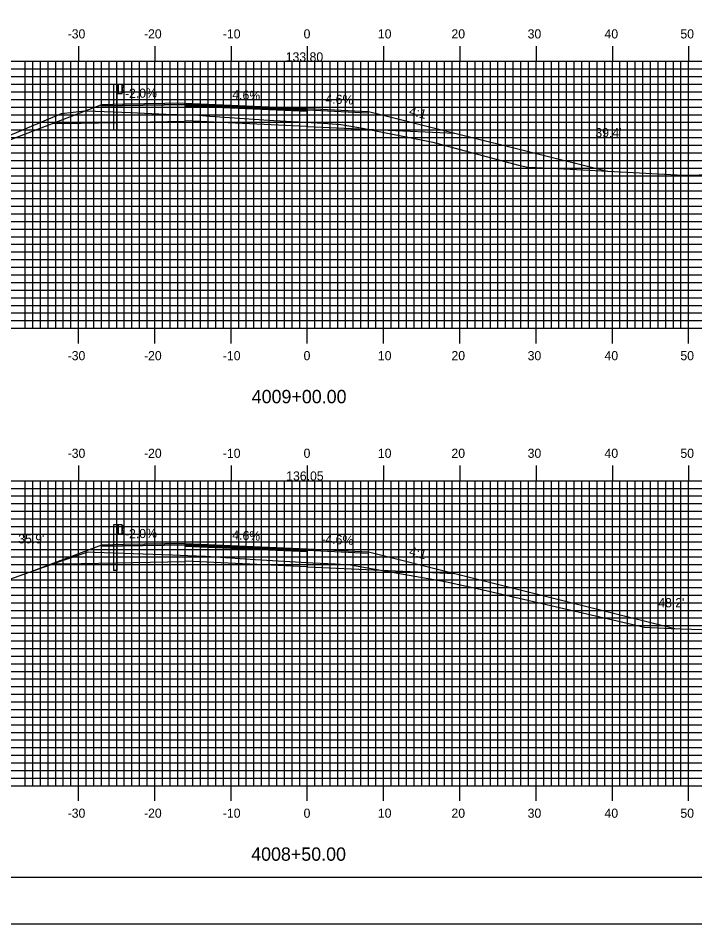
# Model space of a CAD drawing. Extents: x 852147 to 852490, y 364661 to 364881.
# Drawn here: x 852274.8 to 852363.6, y 364661.3 to 364780 of the extents above; entities that cross this region are included whole.
import ezdxf

# ---------------------------------------------------------------- set-up
doc = ezdxf.new("R2010")
doc.units = 0
for name, color, linetype in [('ANNOTATION', 7, 'Continuous'), ('BORDER', 7, 'Continuous'), ('D_Guardrail_Beam_Lt', 7, 'Continuous'), ('D_Roadway_Centerline_Text', 7, 'Continuous'), ('D_Roadway_Edge_Shoulder', 7, 'Continuous'), ('D_Roadway_Edge_TW', 7, 'Continuous'), ('D_Roadway_Pavement', 7, 'Continuous'), ('D_Roadway_SlopeLines', 7, 'Continuous'), ('D_Roadway_SubGrade', 7, 'Continuous'), ('D_Text_Standard', 7, 'Continuous'), ('H_V ANNOTATION', 7, 'Continuous'), ('M_Roadway_Centerline', 7, 'Continuous'), ('MAJOR', 7, 'Continuous'), ('MINOR', 7, 'Continuous'), ('PLOT BOUNDARY', 7, 'Continuous'), ('S_Roadway_Centerline', 7, 'Continuous')]:
    doc.layers.add(name, color=color, linetype=linetype)

msp = doc.modelspace()

# ---------------------------------------------------------------- linework, layer by layer
at = {"layer": 'ANNOTATION'}
msp.add_line((852280.84, 364766.23), (852279.36, 364766.23), dxfattribs=at)
at = {"layer": 'BORDER'}
msp.add_lwpolyline([(852163.16, 364667.37), (852483.16, 364667.37), (852483.16, 364877.37), (852163.16, 364877.37)], close=True, dxfattribs=at)
at = {"layer": 'D_Guardrail_Beam_Lt'}
for p, q in [((852287.33, 364771.33), (852287.33, 364765.33)), ((852287.8, 364771.33), (852287.33, 364771.33)), ((852288.48, 364771.33), (852287.8, 364771.33)), ((852287.8, 364771.33), (852287.8, 364770.16)), ((852287.86, 364771.33), (852287.86, 364770.16)), ((852287.96, 364771.33), (852287.96, 364770.16)), ((852288.48, 364770.16), (852288.48, 364771.33)), ((852288.48, 364771.24), (852288.56, 364771.23)), ((852288.49, 364770.78), (852288.49, 364770.71)), ((852288.72, 364770.98), (852288.52, 364770.84)), ((852288.52, 364770.64), (852288.72, 364770.51)), ((852288.57, 364771.22), (852288.72, 364771.12)), ((852287.8, 364770.16), (852288.48, 364770.16)), ((852287.82, 364765.33), (852287.82, 364770.16)), ((852288.56, 364770.26), (852288.48, 364770.24)), ((852288.72, 364770.36), (852288.57, 364770.26)), ((852287.82, 364765.33), (852287.33, 364765.33)), ((852287.33, 364713.58), (852287.33, 364707.58)), ((852287.8, 364713.58), (852287.33, 364713.58)), ((852288.48, 364713.58), (852287.8, 364713.58)), ((852287.8, 364713.58), (852287.8, 364712.41)), ((852287.86, 364713.58), (852287.86, 364712.41)), ((852287.96, 364713.58), (852287.96, 364712.41)), ((852288.48, 364712.41), (852288.48, 364713.58)), ((852287.8, 364712.41), (852288.48, 364712.41)), ((852287.82, 364707.58), (852287.82, 364712.41)), ((852288.48, 364713.49), (852288.56, 364713.48)), ((852288.56, 364712.51), (852288.48, 364712.49)), ((852288.49, 364713.03), (852288.49, 364712.96)), ((852288.72, 364713.23), (852288.52, 364713.09)), ((852288.52, 364712.89), (852288.72, 364712.76)), ((852288.57, 364713.47), (852288.72, 364713.37)), ((852288.72, 364712.61), (852288.57, 364712.51)), ((852287.82, 364707.58), (852287.33, 364707.58))]:
    msp.add_line(p, q, dxfattribs=at)
for centre, major_axis, start_param, end_param in [((852288.57, 364770.78), (-0.0789, 0), 5.323254, 6.283185), ((852288.57, 364770.71), (-0.0789, 0), 6.283185, 7.243116), ((852288.55, 364771.19), (0.0417, 0), 0.959931, 1.376053), ((852288.67, 364771.05), (0.0877, 0), 5.323254, 7.243116), ((852288.55, 364770.3), (0.0417, 0), 4.907132, 5.323254), ((852288.67, 364770.44), (0.0877, 0), 5.323254, 7.243116), ((852288.57, 364713.03), (-0.0789, 0), 5.323254, 6.283185), ((852288.57, 364712.96), (-0.0789, 0), 6.283185, 7.243116), ((852288.55, 364713.44), (0.0417, 0), 0.959931, 1.376053), ((852288.55, 364712.55), (0.0417, 0), 4.907132, 5.323254), ((852288.67, 364713.3), (0.0877, 0), 5.323254, 7.243116), ((852288.67, 364712.69), (0.0877, 0), 5.323254, 7.243116)]:
    msp.add_ellipse(centre, major_axis=major_axis, ratio=0.995501, start_param=start_param, end_param=end_param, dxfattribs=at)
at = {"layer": 'D_Roadway_Edge_Shoulder'}
for points in [[(852296.76, 364768.9), (852288.76, 364768.74), (852288.76, 364768.74), (852285.76, 364768.68), (852285.76, 364768.52), (852296.76, 364768.71)], [(852296.76, 364711.15), (852288.76, 364710.99), (852288.76, 364710.99), (852285.76, 364710.93), (852285.76, 364710.77), (852296.76, 364710.96)]]:
    msp.add_lwpolyline(points, close=True, dxfattribs=at)
at = {"layer": 'D_Roadway_Edge_TW'}
for p, q in [((852312.76, 364768.17), (852320.76, 364767.8)), ((852312.76, 364710.42), (852320.76, 364710.05))]:
    msp.add_line(p, q, dxfattribs=at)
for points in [[(852296.76, 364768.9), (852312.76, 364768.17), (852312.76, 364768), (852296.76, 364768.71)], [(852296.76, 364711.15), (852312.76, 364710.42), (852312.76, 364710.25), (852296.76, 364710.96)]]:
    msp.add_lwpolyline(points, close=True, dxfattribs=at)
for points in [[(852312.76, 364768), (852320.76, 364767.63), (852320.76, 364767.8)], [(852312.76, 364710.25), (852320.76, 364709.88), (852320.76, 364710.05)]]:
    msp.add_lwpolyline(points, dxfattribs=at)
at = {"layer": 'D_Roadway_Pavement'}
for points in [[(852296.76, 364768.71), (852312.76, 364768), (852312.76, 364767.83), (852296.76, 364768.55)], [(852296.76, 364710.96), (852312.76, 364710.25), (852312.76, 364710.08), (852296.76, 364710.8)]]:
    msp.add_lwpolyline(points, close=True, dxfattribs=at)
for points in [[(852296.76, 364768.71), (852296.76, 364768.55)], [(852312.76, 364768), (852312.76, 364767.83)], [(852312.76, 364768), (852312.76, 364767.83)], [(852296.76, 364710.96), (852296.76, 364710.8)], [(852312.76, 364710.25), (852312.76, 364710.08)], [(852312.76, 364710.25), (852312.76, 364710.08)]]:
    msp.add_lwpolyline(points, dxfattribs=at)
at = {"layer": 'D_Roadway_SlopeLines'}
for p, q in [((852285.76, 364768.68), (852231.3, 364747.76)), ((852285.76, 364710.93), (852276.85, 364707.57)), ((852280.84, 364708.48), (852279.16, 364708.44))]:
    msp.add_line(p, q, dxfattribs=at)
for points in [[(852320.76, 364767.8), (852332.29, 364764.92), (852352.12, 364759.96)], [(852320.76, 364710.05), (852332.29, 364707.17), (852360.97, 364700)]]:
    msp.add_lwpolyline(points, dxfattribs=at)
at = {"layer": 'D_Roadway_SubGrade'}
for p, q in [((852312.76, 364765.83), (852332.05, 364764.97)), ((852312.76, 364708.08), (852332.05, 364707.22))]:
    msp.add_line(p, q, dxfattribs=at)
for points in [[(852280.84, 364766.23), (852296.76, 364766.54), (852296.76, 364768.54), (852296.76, 364768.71), (852285.76, 364768.52), (852285.76, 364768.68)], [(852280.84, 364708.48), (852296.76, 364708.79), (852296.76, 364710.79), (852296.76, 364710.96), (852285.76, 364710.77), (852285.76, 364710.93)]]:
    msp.add_lwpolyline(points, dxfattribs=at)
for points in [[(852296.76, 364768.55), (852312.76, 364767.83), (852312.76, 364765.83), (852296.76, 364766.55)], [(852296.76, 364710.8), (852312.76, 364710.08), (852312.76, 364708.08), (852296.76, 364708.8)]]:
    msp.add_lwpolyline(points, close=True, dxfattribs=at)
at = {"layer": 'MAJOR'}
for p, q in [((852282.76, 364776.37), (852282.76, 364774.37)), ((852292.76, 364776.37), (852292.76, 364774.37)), ((852302.76, 364776.37), (852302.76, 364774.37)), ((852312.76, 364776.37), (852312.76, 364774.37)), ((852322.76, 364776.37), (852322.76, 364774.37)), ((852332.76, 364776.37), (852332.76, 364774.37)), ((852342.76, 364776.37), (852342.76, 364774.37)), ((852352.76, 364776.37), (852352.76, 364774.37)), ((852362.76, 364776.37), (852362.76, 364774.37)), ((852172.76, 364774.37), (852452.76, 364774.37)), ((852172.76, 364774.37), (852452.76, 364774.37)), ((852282.76, 364739.37), (852282.76, 364774.37)), ((852292.76, 364739.37), (852292.76, 364774.37)), ((852302.76, 364739.37), (852302.76, 364774.37)), ((852312.76, 364739.37), (852312.76, 364774.37)), ((852322.76, 364739.37), (852322.76, 364774.37)), ((852332.76, 364739.37), (852332.76, 364774.37)), ((852342.76, 364739.37), (852342.76, 364774.37)), ((852352.76, 364739.37), (852352.76, 364774.37)), ((852362.76, 364739.37), (852362.76, 364774.37)), ((852172.76, 364769.37), (852452.76, 364769.37)), ((852172.76, 364764.37), (852452.76, 364764.37)), ((852172.76, 364759.37), (852452.76, 364759.37)), ((852172.76, 364754.37), (852452.76, 364754.37)), ((852172.76, 364749.37), (852452.76, 364749.37)), ((852172.76, 364744.37), (852452.76, 364744.37)), ((852172.76, 364739.37), (852452.76, 364739.37)), ((852172.76, 364739.37), (852452.76, 364739.37)), ((852282.76, 364737.37), (852282.76, 364739.37)), ((852292.76, 364737.37), (852292.76, 364739.37)), ((852302.76, 364737.37), (852302.76, 364739.37)), ((852312.76, 364737.37), (852312.76, 364739.37)), ((852322.76, 364737.37), (852322.76, 364739.37)), ((852332.76, 364737.37), (852332.76, 364739.37)), ((852342.76, 364737.37), (852342.76, 364739.37)), ((852352.76, 364737.37), (852352.76, 364739.37)), ((852362.76, 364737.37), (852362.76, 364739.37)), ((852282.76, 364721.37), (852282.76, 364719.37)), ((852292.76, 364721.37), (852292.76, 364719.37)), ((852302.76, 364721.37), (852302.76, 364719.37)), ((852312.76, 364721.37), (852312.76, 364719.37)), ((852322.76, 364721.37), (852322.76, 364719.37)), ((852332.76, 364721.37), (852332.76, 364719.37)), ((852342.76, 364721.37), (852342.76, 364719.37)), ((852352.76, 364721.37), (852352.76, 364719.37)), ((852362.76, 364721.37), (852362.76, 364719.37)), ((852172.76, 364719.37), (852452.76, 364719.37)), ((852172.76, 364719.37), (852452.76, 364719.37)), ((852282.76, 364679.37), (852282.76, 364719.37)), ((852292.76, 364679.37), (852292.76, 364719.37)), ((852302.76, 364679.37), (852302.76, 364719.37)), ((852312.76, 364679.37), (852312.76, 364719.37)), ((852322.76, 364679.37), (852322.76, 364719.37)), ((852332.76, 364679.37), (852332.76, 364719.37)), ((852342.76, 364679.37), (852342.76, 364719.37)), ((852352.76, 364679.37), (852352.76, 364719.37)), ((852362.76, 364679.37), (852362.76, 364719.37)), ((852172.76, 364714.37), (852452.76, 364714.37)), ((852172.76, 364709.37), (852452.76, 364709.37)), ((852172.76, 364704.37), (852452.76, 364704.37)), ((852172.76, 364699.37), (852452.76, 364699.37)), ((852172.76, 364694.37), (852452.76, 364694.37)), ((852172.76, 364689.37), (852452.76, 364689.37)), ((852172.76, 364684.37), (852452.76, 364684.37)), ((852172.76, 364679.37), (852452.76, 364679.37)), ((852172.76, 364679.37), (852452.76, 364679.37)), ((852282.76, 364677.37), (852282.76, 364679.37)), ((852292.76, 364677.37), (852292.76, 364679.37)), ((852302.76, 364677.37), (852302.76, 364679.37)), ((852312.76, 364677.37), (852312.76, 364679.37)), ((852322.76, 364677.37), (852322.76, 364679.37)), ((852332.76, 364677.37), (852332.76, 364679.37)), ((852342.76, 364677.37), (852342.76, 364679.37)), ((852352.76, 364677.37), (852352.76, 364679.37)), ((852362.76, 364677.37), (852362.76, 364679.37))]:
    msp.add_line(p, q, dxfattribs=at)
at = {"layer": 'MINOR'}
for p, q in [((852275.76, 364739.37), (852275.76, 364774.37)), ((852276.76, 364739.37), (852276.76, 364774.37)), ((852277.76, 364739.37), (852277.76, 364774.37)), ((852278.76, 364739.37), (852278.76, 364774.37)), ((852279.76, 364739.37), (852279.76, 364774.37)), ((852280.76, 364739.37), (852280.76, 364774.37)), ((852281.76, 364739.37), (852281.76, 364774.37)), ((852283.76, 364739.37), (852283.76, 364774.37)), ((852284.76, 364739.37), (852284.76, 364774.37)), ((852285.76, 364739.37), (852285.76, 364774.37)), ((852286.76, 364739.37), (852286.76, 364774.37)), ((852287.76, 364739.37), (852287.76, 364774.37)), ((852288.76, 364739.37), (852288.76, 364774.37)), ((852289.76, 364739.37), (852289.76, 364774.37)), ((852290.76, 364739.37), (852290.76, 364774.37)), ((852291.76, 364739.37), (852291.76, 364774.37)), ((852293.76, 364739.37), (852293.76, 364774.37)), ((852294.76, 364739.37), (852294.76, 364774.37)), ((852295.76, 364739.37), (852295.76, 364774.37)), ((852296.76, 364739.37), (852296.76, 364774.37)), ((852297.76, 364739.37), (852297.76, 364774.37)), ((852298.76, 364739.37), (852298.76, 364774.37)), ((852299.76, 364739.37), (852299.76, 364774.37)), ((852300.76, 364739.37), (852300.76, 364774.37)), ((852301.76, 364739.37), (852301.76, 364774.37)), ((852303.76, 364739.37), (852303.76, 364774.37)), ((852304.76, 364739.37), (852304.76, 364774.37)), ((852305.76, 364739.37), (852305.76, 364774.37)), ((852306.76, 364739.37), (852306.76, 364774.37)), ((852307.76, 364739.37), (852307.76, 364774.37)), ((852308.76, 364739.37), (852308.76, 364774.37)), ((852309.76, 364739.37), (852309.76, 364774.37)), ((852310.76, 364739.37), (852310.76, 364774.37)), ((852311.76, 364739.37), (852311.76, 364774.37)), ((852313.76, 364739.37), (852313.76, 364774.37)), ((852314.76, 364739.37), (852314.76, 364774.37)), ((852315.76, 364739.37), (852315.76, 364774.37)), ((852316.76, 364739.37), (852316.76, 364774.37)), ((852317.76, 364739.37), (852317.76, 364774.37)), ((852318.76, 364739.37), (852318.76, 364774.37)), ((852319.76, 364739.37), (852319.76, 364774.37)), ((852320.76, 364739.37), (852320.76, 364774.37)), ((852321.76, 364739.37), (852321.76, 364774.37)), ((852323.76, 364739.37), (852323.76, 364774.37)), ((852324.76, 364739.37), (852324.76, 364774.37)), ((852325.76, 364739.37), (852325.76, 364774.37)), ((852326.76, 364739.37), (852326.76, 364774.37)), ((852327.76, 364739.37), (852327.76, 364774.37)), ((852328.76, 364739.37), (852328.76, 364774.37)), ((852329.76, 364739.37), (852329.76, 364774.37)), ((852330.76, 364739.37), (852330.76, 364774.37)), ((852331.76, 364739.37), (852331.76, 364774.37)), ((852333.76, 364739.37), (852333.76, 364774.37)), ((852334.76, 364739.37), (852334.76, 364774.37)), ((852335.76, 364739.37), (852335.76, 364774.37)), ((852336.76, 364739.37), (852336.76, 364774.37)), ((852337.76, 364739.37), (852337.76, 364774.37)), ((852338.76, 364739.37), (852338.76, 364774.37)), ((852339.76, 364739.37), (852339.76, 364774.37)), ((852340.76, 364739.37), (852340.76, 364774.37)), ((852341.76, 364739.37), (852341.76, 364774.37)), ((852343.76, 364739.37), (852343.76, 364774.37)), ((852344.76, 364739.37), (852344.76, 364774.37)), ((852345.76, 364739.37), (852345.76, 364774.37)), ((852346.76, 364739.37), (852346.76, 364774.37)), ((852347.76, 364739.37), (852347.76, 364774.37)), ((852348.76, 364739.37), (852348.76, 364774.37)), ((852349.76, 364739.37), (852349.76, 364774.37)), ((852350.76, 364739.37), (852350.76, 364774.37)), ((852351.76, 364739.37), (852351.76, 364774.37)), ((852353.76, 364739.37), (852353.76, 364774.37)), ((852354.76, 364739.37), (852354.76, 364774.37)), ((852355.76, 364739.37), (852355.76, 364774.37)), ((852356.76, 364739.37), (852356.76, 364774.37)), ((852357.76, 364739.37), (852357.76, 364774.37)), ((852358.76, 364739.37), (852358.76, 364774.37)), ((852359.76, 364739.37), (852359.76, 364774.37)), ((852360.76, 364739.37), (852360.76, 364774.37)), ((852361.76, 364739.37), (852361.76, 364774.37)), ((852172.76, 364773.37), (852452.76, 364773.37)), ((852172.76, 364772.37), (852452.76, 364772.37)), ((852172.76, 364771.37), (852452.76, 364771.37)), ((852172.76, 364770.37), (852452.76, 364770.37)), ((852172.76, 364768.37), (852452.76, 364768.37)), ((852172.76, 364767.37), (852452.76, 364767.37)), ((852172.76, 364766.37), (852452.76, 364766.37)), ((852172.76, 364765.37), (852452.76, 364765.37)), ((852172.76, 364763.37), (852452.76, 364763.37)), ((852172.76, 364762.37), (852452.76, 364762.37)), ((852172.76, 364761.37), (852452.76, 364761.37)), ((852172.76, 364760.37), (852452.76, 364760.37)), ((852172.76, 364758.37), (852452.76, 364758.37)), ((852172.76, 364757.37), (852452.76, 364757.37)), ((852172.76, 364756.37), (852452.76, 364756.37)), ((852172.76, 364755.37), (852452.76, 364755.37)), ((852172.76, 364753.37), (852452.76, 364753.37)), ((852172.76, 364752.37), (852452.76, 364752.37)), ((852172.76, 364751.37), (852452.76, 364751.37)), ((852172.76, 364750.37), (852452.76, 364750.37)), ((852172.76, 364748.37), (852452.76, 364748.37)), ((852172.76, 364747.37), (852452.76, 364747.37)), ((852172.76, 364746.37), (852452.76, 364746.37)), ((852172.76, 364745.37), (852452.76, 364745.37)), ((852172.76, 364743.37), (852452.76, 364743.37)), ((852172.76, 364742.37), (852452.76, 364742.37)), ((852172.76, 364741.37), (852452.76, 364741.37)), ((852172.76, 364740.37), (852452.76, 364740.37)), ((852172.76, 364718.37), (852452.76, 364718.37)), ((852275.76, 364679.37), (852275.76, 364719.37)), ((852276.76, 364679.37), (852276.76, 364719.37)), ((852277.76, 364679.37), (852277.76, 364719.37)), ((852278.76, 364679.37), (852278.76, 364719.37)), ((852279.76, 364679.37), (852279.76, 364719.37)), ((852280.76, 364679.37), (852280.76, 364719.37)), ((852281.76, 364679.37), (852281.76, 364719.37)), ((852283.76, 364679.37), (852283.76, 364719.37)), ((852284.76, 364679.37), (852284.76, 364719.37)), ((852285.76, 364679.37), (852285.76, 364719.37)), ((852286.76, 364679.37), (852286.76, 364719.37)), ((852287.76, 364679.37), (852287.76, 364719.37)), ((852288.76, 364679.37), (852288.76, 364719.37)), ((852289.76, 364679.37), (852289.76, 364719.37)), ((852290.76, 364679.37), (852290.76, 364719.37)), ((852291.76, 364679.37), (852291.76, 364719.37)), ((852293.76, 364679.37), (852293.76, 364719.37)), ((852294.76, 364679.37), (852294.76, 364719.37)), ((852295.76, 364679.37), (852295.76, 364719.37)), ((852296.76, 364679.37), (852296.76, 364719.37)), ((852297.76, 364679.37), (852297.76, 364719.37)), ((852298.76, 364679.37), (852298.76, 364719.37)), ((852299.76, 364679.37), (852299.76, 364719.37)), ((852300.76, 364679.37), (852300.76, 364719.37)), ((852301.76, 364679.37), (852301.76, 364719.37)), ((852303.76, 364679.37), (852303.76, 364719.37)), ((852304.76, 364679.37), (852304.76, 364719.37)), ((852305.76, 364679.37), (852305.76, 364719.37)), ((852306.76, 364679.37), (852306.76, 364719.37)), ((852307.76, 364679.37), (852307.76, 364719.37)), ((852308.76, 364679.37), (852308.76, 364719.37)), ((852309.76, 364679.37), (852309.76, 364719.37)), ((852310.76, 364679.37), (852310.76, 364719.37)), ((852311.76, 364679.37), (852311.76, 364719.37)), ((852313.76, 364679.37), (852313.76, 364719.37)), ((852314.76, 364679.37), (852314.76, 364719.37)), ((852315.76, 364679.37), (852315.76, 364719.37)), ((852316.76, 364679.37), (852316.76, 364719.37)), ((852317.76, 364679.37), (852317.76, 364719.37)), ((852318.76, 364679.37), (852318.76, 364719.37)), ((852319.76, 364679.37), (852319.76, 364719.37)), ((852320.76, 364679.37), (852320.76, 364719.37)), ((852321.76, 364679.37), (852321.76, 364719.37)), ((852323.76, 364679.37), (852323.76, 364719.37)), ((852324.76, 364679.37), (852324.76, 364719.37)), ((852325.76, 364679.37), (852325.76, 364719.37)), ((852326.76, 364679.37), (852326.76, 364719.37)), ((852327.76, 364679.37), (852327.76, 364719.37)), ((852328.76, 364679.37), (852328.76, 364719.37)), ((852329.76, 364679.37), (852329.76, 364719.37)), ((852330.76, 364679.37), (852330.76, 364719.37)), ((852331.76, 364679.37), (852331.76, 364719.37)), ((852333.76, 364679.37), (852333.76, 364719.37)), ((852334.76, 364679.37), (852334.76, 364719.37)), ((852335.76, 364679.37), (852335.76, 364719.37)), ((852336.76, 364679.37), (852336.76, 364719.37)), ((852337.76, 364679.37), (852337.76, 364719.37)), ((852338.76, 364679.37), (852338.76, 364719.37)), ((852339.76, 364679.37), (852339.76, 364719.37)), ((852340.76, 364679.37), (852340.76, 364719.37)), ((852341.76, 364679.37), (852341.76, 364719.37)), ((852343.76, 364679.37), (852343.76, 364719.37)), ((852344.76, 364679.37), (852344.76, 364719.37)), ((852345.76, 364679.37), (852345.76, 364719.37)), ((852346.76, 364679.37), (852346.76, 364719.37)), ((852347.76, 364679.37), (852347.76, 364719.37)), ((852348.76, 364679.37), (852348.76, 364719.37)), ((852349.76, 364679.37), (852349.76, 364719.37)), ((852350.76, 364679.37), (852350.76, 364719.37)), ((852351.76, 364679.37), (852351.76, 364719.37)), ((852353.76, 364679.37), (852353.76, 364719.37)), ((852354.76, 364679.37), (852354.76, 364719.37)), ((852355.76, 364679.37), (852355.76, 364719.37)), ((852356.76, 364679.37), (852356.76, 364719.37)), ((852357.76, 364679.37), (852357.76, 364719.37)), ((852358.76, 364679.37), (852358.76, 364719.37)), ((852359.76, 364679.37), (852359.76, 364719.37)), ((852360.76, 364679.37), (852360.76, 364719.37)), ((852361.76, 364679.37), (852361.76, 364719.37)), ((852172.76, 364717.37), (852452.76, 364717.37)), ((852172.76, 364716.37), (852452.76, 364716.37)), ((852172.76, 364715.37), (852452.76, 364715.37)), ((852172.76, 364713.37), (852452.76, 364713.37)), ((852172.76, 364712.37), (852452.76, 364712.37)), ((852172.76, 364711.37), (852452.76, 364711.37)), ((852172.76, 364710.37), (852452.76, 364710.37)), ((852172.76, 364708.37), (852452.76, 364708.37)), ((852172.76, 364707.37), (852452.76, 364707.37)), ((852172.76, 364706.37), (852452.76, 364706.37)), ((852172.76, 364705.37), (852452.76, 364705.37)), ((852172.76, 364703.37), (852452.76, 364703.37)), ((852172.76, 364702.37), (852452.76, 364702.37)), ((852172.76, 364701.37), (852452.76, 364701.37)), ((852172.76, 364700.37), (852452.76, 364700.37)), ((852172.76, 364698.37), (852452.76, 364698.37)), ((852172.76, 364697.37), (852452.76, 364697.37)), ((852172.76, 364696.37), (852452.76, 364696.37)), ((852172.76, 364695.37), (852452.76, 364695.37)), ((852172.76, 364693.37), (852452.76, 364693.37)), ((852172.76, 364692.37), (852452.76, 364692.37)), ((852172.76, 364691.37), (852452.76, 364691.37)), ((852172.76, 364690.37), (852452.76, 364690.37)), ((852172.76, 364688.37), (852452.76, 364688.37)), ((852172.76, 364687.37), (852452.76, 364687.37)), ((852172.76, 364686.37), (852452.76, 364686.37)), ((852172.76, 364685.37), (852452.76, 364685.37)), ((852172.76, 364683.37), (852452.76, 364683.37)), ((852172.76, 364682.37), (852452.76, 364682.37)), ((852172.76, 364681.37), (852452.76, 364681.37)), ((852172.76, 364680.37), (852452.76, 364680.37))]:
    msp.add_line(p, q, dxfattribs=at)
at = {"layer": 'PLOT BOUNDARY'}
msp.add_lwpolyline([(852146.97, 364661.25), (852486.97, 364661.25), (852486.97, 364881.25), (852146.97, 364881.25)], close=True, dxfattribs=at)
at = {"layer": 'S_Roadway_Centerline'}
for points in [[(852259.46, 364758.66), (852280.54, 364767.54), (852283.59, 364767.89), (852283.84, 364767.87), (852289.58, 364767.66), (852294.22, 364767.46), (852298.53, 364767.29), (852299.99, 364767.18), (852308.35, 364766.6), (852314.88, 364766.27), (852317.16, 364766.08), (852319.76, 364765.65), (852329.21, 364763.76), (852340.44, 364760.77), (852341.66, 364760.49), (852345.55, 364760.31), (852361.27, 364759.47), (852363.41, 364759.46), (852366.4, 364759.6)], [(852228.88, 364694.73), (852235.14, 364697.36), (852236.84, 364698.07), (852239.27, 364698.72), (852249.31, 364700.62), (852254.2, 364701.02), (852260.43, 364701.74), (852280.28, 364708.79), (852284.03, 364710.04), (852284.87, 364710.01), (852295.09, 364709.66), (852297.1, 364709.56), (852299.39, 364709.49), (852305.93, 364709.05), (852313.49, 364708.62), (852316.43, 364708.48), (852318.4, 364708.34), (852330.85, 364706.15), (852335.84, 364705.07), (852344.14, 364703.12), (852356.99, 364700.16), (852360.48, 364700.01), (852373.76, 364699.54)]]:
    msp.add_lwpolyline(points, dxfattribs=at)

# ---------------------------------------------------------------- texts
at = {"layer": 'ANNOTATION'}
for s, rotation, p in [('-2.0%', 1.1458, (852288.86, 364769.55)), ('4.6%', 357.3663, (852302.9, 364769.42)), ('-4.6%', 357.3663, (852314.58, 364768.89)), ('4:1', 345.9638, (852326.03, 364767.34)), ('-2.0%', 1.1458, (852288.86, 364711.8)), ('4.6%', 357.3663, (852302.9, 364711.67)), ('-4.6%', 357.3663, (852314.58, 364711.14)), ('4:1', 345.9638, (852326.03, 364709.59))]:
    msp.add_text(s, height=1.2, rotation=rotation, dxfattribs=at).set_placement(p)
at = {"layer": 'D_Roadway_Centerline_Text'}
for s, p in [('133.80', (852309.93, 364774.35)), ('136.05', (852309.99, 364719.39))]:
    msp.add_text(s, height=1.2, dxfattribs=at).set_placement(p)
at = {"layer": 'D_Text_Standard'}
for s, p in [("39.4'", (852350.53, 364764.41)), ("35.9'", (852274.85, 364711.15)), ("48.2'", (852358.78, 364702.77))]:
    msp.add_text(s, height=1.2, dxfattribs=at).set_placement(p)
at = {"layer": 'H_V ANNOTATION'}
for s, height, p in [('-30', 1.2, (852281.33, 364777.37)), ('-20', 1.2, (852291.34, 364777.37)), ('-10', 1.2, (852301.68, 364777.37)), ('0', 1.2, (852312.27, 364777.37)), ('10', 1.2, (852322.01, 364777.37)), ('20', 1.2, (852331.66, 364777.37)), ('30', 1.2, (852341.65, 364777.37)), ('40', 1.2, (852351.73, 364777.37)), ('50', 1.2, (852361.68, 364777.37)), ('-30', 1.2, (852281.33, 364735.17)), ('-20', 1.2, (852291.34, 364735.17)), ('-10', 1.2, (852301.68, 364735.17)), ('0', 1.2, (852312.27, 364735.17)), ('10', 1.2, (852322.01, 364735.17)), ('20', 1.2, (852331.66, 364735.17)), ('30', 1.2, (852341.65, 364735.17)), ('40', 1.2, (852351.73, 364735.17)), ('50', 1.2, (852361.68, 364735.17)), ('4009+00.00', 1.75, (852305.47, 364729.53)), ('-30', 1.2, (852281.33, 364722.37)), ('-20', 1.2, (852291.34, 364722.37)), ('-10', 1.2, (852301.68, 364722.37)), ('0', 1.2, (852312.27, 364722.37)), ('10', 1.2, (852322.01, 364722.37)), ('20', 1.2, (852331.66, 364722.37)), ('30', 1.2, (852341.65, 364722.37)), ('40', 1.2, (852351.73, 364722.37)), ('50', 1.2, (852361.68, 364722.37)), ('-30', 1.2, (852281.33, 364675.17)), ('-20', 1.2, (852291.34, 364675.17)), ('-10', 1.2, (852301.68, 364675.17)), ('0', 1.2, (852312.27, 364675.17)), ('10', 1.2, (852322.01, 364675.17)), ('20', 1.2, (852331.66, 364675.17)), ('30', 1.2, (852341.65, 364675.17)), ('40', 1.2, (852351.73, 364675.17)), ('50', 1.2, (852361.68, 364675.17)), ('4008+50.00', 1.75, (852305.4, 364669.53))]:
    msp.add_text(s, height=height, dxfattribs=at).set_placement(p)
at = {"layer": 'M_Roadway_Centerline'}
for s, p in [('C', (852298.53, 364767.29)), ('L', (852298.53, 364767.29)), ('C', (852299.38, 364709.49)), ('L', (852299.39, 364709.49))]:
    msp.add_text(s, height=0.0146, dxfattribs=at).set_placement(p)

doc.saveas('drawing.dxf')
